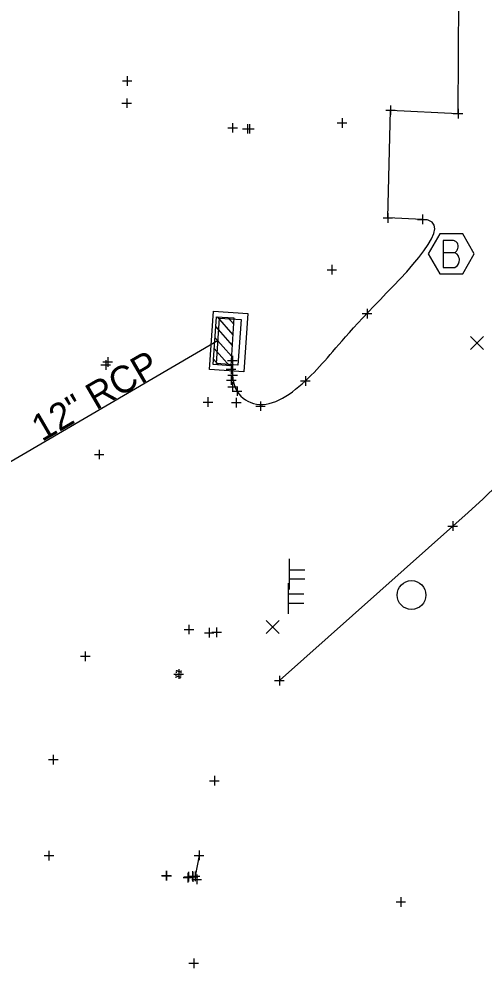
# Model space of a CAD drawing. Extents: x 2188719 to 2189819, y 654569 to 659504.
# Drawn here: x 2189350.5 to 2189399, y 655564.7 to 655663.5 of the extents above; entities that cross this region are included whole.
import ezdxf

# ---------------------------------------------------------------- set-up
doc = ezdxf.new("R2010")
doc.units = 0
for name, color, linetype in [('DR_X_Cells', 7, 'Continuous'), ('DR_X_Storm_Sewer', 7, 'Continuous'), ('DR_X_Text', 7, 'Continuous'), ('GK_Drainage_Nodes', 7, 'Continuous'), ('PM_X_Cells', 7, 'Continuous'), ('RD_X_Cells', 7, 'Continuous'), ('RD_X_Concrete_Pad', 7, 'Continuous'), ('RD_X_GR_Lt', 7, 'Continuous'), ('SN_X_Public', 7, 'Continuous'), ('SV_P_Mon_Cells_Set', 7, 'Continuous'), ('SV_X_Random_Point', 7, 'Continuous'), ('SV_X_Shot_Marker', 7, 'Continuous')]:
    doc.layers.add(name, color=color, linetype=linetype)

msp = doc.modelspace()

# ---------------------------------------------------------------- linework, layer by layer
at = {"layer": 'DR_X_Cells'}
for p, q in [((2189371.195, 655632.495), (2189372.833, 655630.627)), ((2189372.326, 655632.419), (2189372.909, 655631.755)), ((2189371.05, 655631.447), (2189372.757, 655629.5)), ((2189370.975, 655630.32), (2189372.682, 655628.373)), ((2189370.899, 655629.192), (2189372.472, 655627.398)), ((2189370.824, 655628.065), (2189371.342, 655627.474))]:
    msp.add_line(p, q, dxfattribs=at)
for points in [[(2189374.401, 655632.823), (2189373.994, 655626.753), (2189370.418, 655626.993), (2189370.825, 655633.063)], [(2189372.95, 655632.377), (2189372.616, 655627.389), (2189370.786, 655627.511), (2189371.121, 655632.5)], [(2189373.69, 655632.202), (2189373.372, 655627.463), (2189371.127, 655627.614), (2189371.445, 655632.353)]]:
    msp.add_lwpolyline(points, close=True, dxfattribs=at)
at = {"layer": 'DR_X_Storm_Sewer'}
msp.add_line((2189371.314, 655630.005), (2189348.002, 655616.423), dxfattribs=at)
at = {"layer": 'GK_Drainage_Nodes'}
for p, q in [((2189372.568, 655632.278), (2189372.568, 655632.278)), ((2189370.621, 655630.028), (2189370.621, 655630.028)), ((2189371.286, 655629.983), (2189371.286, 655629.983)), ((2189372.409, 655629.908), (2189372.409, 655629.908)), ((2189372.783, 655629.883), (2189372.783, 655629.883)), ((2189372.783, 655629.883), (2189372.783, 655629.883)), ((2189373.531, 655629.833), (2189373.531, 655629.833)), ((2189374.196, 655629.788), (2189374.196, 655629.788)), ((2189372.25, 655627.538), (2189372.25, 655627.538))]:
    msp.add_line(p, q, dxfattribs=at)
at = {"layer": 'PM_X_Cells'}
for p, q in [((2189366.905, 655594.935), (2189366.917, 655595.034)), ((2189366.924, 655595.102), (2189366.936, 655595.201)), ((2189366.944, 655595.268), (2189366.955, 655595.368)), ((2189366.963, 655595.435), (2189366.974, 655595.534)), ((2189366.982, 655595.601), (2189366.994, 655595.701)), ((2189367.192, 655595.29), (2189367.192, 655595.29)), ((2189367.41, 655595.046), (2189367.421, 655595.145)), ((2189367.429, 655595.212), (2189367.44, 655595.312)), ((2189367.448, 655595.379), (2189367.46, 655595.478)), ((2189367.467, 655595.545), (2189367.479, 655595.645)), ((2189367.39, 655594.879), (2189367.402, 655594.978))]:
    msp.add_line(p, q, dxfattribs=at)
for centre, start, end in [((2189367.254, 655595.824), 205.38356, 221.32603), ((2189367.13, 655594.756), 102.29753, 118.23046), ((2189367.254, 655595.824), 228.58791, 244.5195), ((2189367.13, 655594.756), 71.80011, 95.02993), ((2189367.254, 655595.824), 251.79129, 275.01886), ((2189367.254, 655595.824), 282.2969, 298.23046), ((2189367.254, 655595.824), 305.49145, 321.43588), ((2189367.13, 655594.756), 125.4944, 141.43588), ((2189367.13, 655594.756), 48.58791, 64.5208), ((2189367.13, 655594.756), 25.38356, 41.33027)]:
    msp.add_arc(centre, 0.288, start, end, dxfattribs=at)
at = {"layer": 'RD_X_Cells'}
for p, q in [((2189394.398, 655641.111), (2189393.198, 655639.032)), ((2189396.798, 655641.111), (2189394.398, 655641.111)), ((2189397.998, 655639.032), (2189396.798, 655641.111)), ((2189393.198, 655639.032), (2189394.398, 655636.954)), ((2189396.798, 655636.954), (2189397.998, 655639.032)), ((2189394.398, 655636.954), (2189396.798, 655636.954))]:
    msp.add_line(p, q, dxfattribs=at)
msp.add_lwpolyline([(2189395.962, 655639.153), (2189396.072, 655639.264), (2189396.138, 655639.33), (2189396.182, 655639.396), (2189396.204, 655639.44), (2189396.248, 655639.528), (2189396.27, 655639.594), (2189396.314, 655639.749), (2189396.314, 655639.815), (2189396.314, 655639.903), (2189396.293, 655640.035), (2189396.248, 655640.145), (2189396.182, 655640.234), (2189396.072, 655640.322), (2189395.984, 655640.366), (2189395.94, 655640.388), (2189395.829, 655640.432), (2189394.749, 655640.432), (2189394.749, 655637.632), (2189395.962, 655637.632), (2189396.116, 655637.72), (2189396.248, 655637.83), (2189396.358, 655638.007), (2189396.425, 655638.205), (2189396.447, 655638.404), (2189396.447, 655638.536), (2189396.403, 655638.668), (2189396.314, 655638.867), (2189396.204, 655638.999), (2189395.962, 655639.153), (2189394.749, 655639.153)], dxfattribs=at)
at = {"layer": 'RD_X_Concrete_Pad'}
for p, q in [((2189396.311, 655653.642), (2189396.425, 655669.553)), ((2189388.989, 655642.786), (2189389.271, 655654.003)), ((2189389.271, 655654.003), (2189396.311, 655653.642)), ((2189392.587, 655642.629), (2189388.989, 655642.786)), ((2189372.787, 655627.939), (2189372.818, 655626.395))]:
    msp.add_line(p, q, dxfattribs=at)
msp.add_open_spline([(2189372.818, 655626.395), (2189372.859, 655624.351), (2189376.129, 655621.909), (2189382.032, 655627.122), (2189385.284, 655631.64), (2189396.44, 655642.461), (2189392.587, 655642.629)], degree=3, dxfattribs=at)
at = {"layer": 'RD_X_GR_Lt'}
for p, q in [((2189395.751, 655610.7), (2189377.69, 655594.617)), ((2189369.32, 655576.413), (2189368.896, 655574.24))]:
    msp.add_line(p, q, dxfattribs=at)
msp.add_arc((2189352.785, 655661.984), 66.904, 309.95614, 7.43625, dxfattribs=at)
at = {"layer": 'SN_X_Public'}
for p, q in [((2189378.726, 655604.08), (2189378.726, 655607.28)), ((2189378.726, 655606.16), (2189380.326, 655606.16)), ((2189378.726, 655605.68), (2189378.726, 655605.68)), ((2189378.726, 655605.2), (2189380.326, 655605.2)), ((2189378.626, 655601.55), (2189378.626, 655604.75)), ((2189378.626, 655603.63), (2189380.226, 655603.63)), ((2189378.626, 655603.15), (2189378.626, 655603.15)), ((2189378.626, 655602.67), (2189380.226, 655602.67))]:
    msp.add_line(p, q, dxfattribs=at)
at = {"layer": 'SV_P_Mon_Cells_Set'}
msp.add_circle((2189391.464, 655603.518), 1.5, dxfattribs=at)
at = {"layer": 'SV_X_Random_Point'}
for p, q in [((2189397.613, 655629.098), (2189398.947, 655630.433)), ((2189397.613, 655630.433), (2189398.947, 655629.098)), ((2189376.325, 655599.531), (2189377.659, 655600.867)), ((2189376.325, 655600.867), (2189377.659, 655599.531))]:
    msp.add_line(p, q, dxfattribs=at)
at = {"layer": 'SV_X_Shot_Marker'}
for p, q in [((2189361.822, 655657.547), (2189361.822, 655656.547)), ((2189361.322, 655657.047), (2189362.322, 655657.047)), ((2189361.822, 655657.047), (2189361.822, 655657.047)), ((2189361.276, 655654.728), (2189362.276, 655654.728)), ((2189361.776, 655655.228), (2189361.776, 655654.228)), ((2189361.776, 655654.728), (2189361.776, 655654.728)), ((2189389.271, 655654.503), (2189389.271, 655653.503)), ((2189388.771, 655654.003), (2189389.771, 655654.003)), ((2189389.271, 655654.003), (2189389.271, 655654.003)), ((2189395.811, 655653.642), (2189396.811, 655653.642)), ((2189396.311, 655654.142), (2189396.311, 655653.142)), ((2189396.311, 655653.642), (2189396.311, 655653.642)), ((2189372.812, 655652.663), (2189372.812, 655651.663)), ((2189374.36, 655652.557), (2189374.36, 655651.557)), ((2189374.567, 655652.555), (2189374.567, 655651.555)), ((2189383.721, 655652.672), (2189384.721, 655652.672)), ((2189384.221, 655653.172), (2189384.221, 655652.172)), ((2189384.221, 655652.672), (2189384.221, 655652.672)), ((2189372.312, 655652.163), (2189373.312, 655652.163)), ((2189372.812, 655652.163), (2189372.812, 655652.163)), ((2189373.86, 655652.057), (2189374.86, 655652.057)), ((2189374.067, 655652.055), (2189375.067, 655652.055)), ((2189374.36, 655652.057), (2189374.36, 655652.057)), ((2189374.567, 655652.055), (2189374.567, 655652.055)), ((2189388.489, 655642.786), (2189389.489, 655642.786)), ((2189388.989, 655643.286), (2189388.989, 655642.286)), ((2189388.989, 655642.786), (2189388.989, 655642.786)), ((2189392.087, 655642.629), (2189393.087, 655642.629)), ((2189392.587, 655643.129), (2189392.587, 655642.129)), ((2189392.587, 655642.629), (2189392.587, 655642.629)), ((2189383.153, 655637.886), (2189383.153, 655636.886)), ((2189382.653, 655637.386), (2189383.653, 655637.386)), ((2189383.153, 655637.386), (2189383.153, 655637.386)), ((2189386.327, 655632.815), (2189387.327, 655632.815)), ((2189386.827, 655633.315), (2189386.827, 655632.315)), ((2189386.827, 655632.815), (2189386.827, 655632.815)), ((2189359.294, 655627.783), (2189360.294, 655627.783)), ((2189359.583, 655627.97), (2189359.583, 655626.97)), ((2189359.794, 655628.283), (2189359.794, 655627.283)), ((2189359.794, 655627.783), (2189359.794, 655627.783)), ((2189372.287, 655627.939), (2189373.287, 655627.939)), ((2189372.287, 655627.939), (2189373.287, 655627.939)), ((2189372.787, 655628.439), (2189372.787, 655627.439)), ((2189372.787, 655628.439), (2189372.787, 655627.439)), ((2189372.787, 655627.939), (2189372.787, 655627.939)), ((2189372.787, 655627.939), (2189372.787, 655627.939)), ((2189359.083, 655627.47), (2189360.083, 655627.47)), ((2189359.583, 655627.47), (2189359.583, 655627.47)), ((2189372.15, 655627.019), (2189373.15, 655627.019)), ((2189372.65, 655627.519), (2189372.65, 655626.519)), ((2189372.65, 655627.019), (2189372.65, 655627.019)), ((2189372.818, 655626.895), (2189372.818, 655625.895)), ((2189372.167, 655625.903), (2189373.167, 655625.903)), ((2189372.318, 655626.395), (2189373.318, 655626.395)), ((2189372.667, 655626.403), (2189372.667, 655625.403)), ((2189372.667, 655625.903), (2189372.667, 655625.903)), ((2189372.804, 655625.71), (2189372.804, 655624.71)), ((2189372.818, 655626.395), (2189372.818, 655626.395)), ((2189379.905, 655625.807), (2189380.905, 655625.807)), ((2189380.405, 655626.307), (2189380.405, 655625.307)), ((2189380.405, 655625.807), (2189380.405, 655625.807)), ((2189372.304, 655625.21), (2189373.304, 655625.21)), ((2189372.784, 655624.746), (2189373.784, 655624.746)), ((2189372.804, 655625.21), (2189372.804, 655625.21)), ((2189373.284, 655625.246), (2189373.284, 655624.246)), ((2189373.284, 655624.746), (2189373.284, 655624.746)), ((2189370.24, 655624.114), (2189370.24, 655623.114)), ((2189373.188, 655624.059), (2189373.188, 655623.059)), ((2189369.74, 655623.614), (2189370.74, 655623.614)), ((2189370.24, 655623.614), (2189370.24, 655623.614)), ((2189372.688, 655623.559), (2189373.688, 655623.559)), ((2189373.188, 655623.559), (2189373.188, 655623.559)), ((2189375.222, 655623.182), (2189376.222, 655623.182)), ((2189375.722, 655623.682), (2189375.722, 655622.682)), ((2189375.722, 655623.182), (2189375.722, 655623.182)), ((2189358.408, 655618.152), (2189359.408, 655618.152)), ((2189358.908, 655618.652), (2189358.908, 655617.652)), ((2189358.908, 655618.152), (2189358.908, 655618.152)), ((2189395.751, 655611.2), (2189395.751, 655610.2)), ((2189395.251, 655610.7), (2189396.251, 655610.7)), ((2189395.751, 655610.7), (2189395.751, 655610.7)), ((2189368.261, 655600.43), (2189368.261, 655599.43)), ((2189370.372, 655600.096), (2189370.372, 655599.096)), ((2189371.141, 655600.145), (2189371.141, 655599.145)), ((2189367.761, 655599.93), (2189368.761, 655599.93)), ((2189368.261, 655599.93), (2189368.261, 655599.93)), ((2189369.872, 655599.596), (2189370.872, 655599.596)), ((2189370.372, 655599.596), (2189370.372, 655599.596)), ((2189370.641, 655599.645), (2189371.641, 655599.645)), ((2189371.141, 655599.645), (2189371.141, 655599.645)), ((2189356.954, 655597.149), (2189357.954, 655597.149)), ((2189357.454, 655597.649), (2189357.454, 655596.649)), ((2189357.454, 655597.149), (2189357.454, 655597.149)), ((2189366.692, 655595.29), (2189367.692, 655595.29)), ((2189367.192, 655595.79), (2189367.192, 655594.79)), ((2189367.192, 655595.29), (2189367.192, 655595.29)), ((2189377.69, 655595.117), (2189377.69, 655594.117)), ((2189377.19, 655594.617), (2189378.19, 655594.617)), ((2189377.69, 655594.617), (2189377.69, 655594.617)), ((2189353.622, 655586.391), (2189354.622, 655586.391)), ((2189354.122, 655586.891), (2189354.122, 655585.891)), ((2189354.122, 655586.391), (2189354.122, 655586.391)), ((2189370.413, 655584.182), (2189371.413, 655584.182)), ((2189370.913, 655584.682), (2189370.913, 655583.682)), ((2189370.913, 655584.182), (2189370.913, 655584.182)), ((2189353.171, 655576.389), (2189354.171, 655576.389)), ((2189353.671, 655576.889), (2189353.671, 655575.889)), ((2189353.671, 655576.389), (2189353.671, 655576.389)), ((2189368.82, 655576.413), (2189369.82, 655576.413)), ((2189369.32, 655576.913), (2189369.32, 655575.913)), ((2189369.32, 655576.413), (2189369.32, 655576.413)), ((2189365.394, 655574.312), (2189366.394, 655574.312)), ((2189365.43, 655574.301), (2189366.43, 655574.301)), ((2189365.894, 655574.812), (2189365.894, 655573.812)), ((2189365.894, 655574.312), (2189365.894, 655574.312)), ((2189365.93, 655574.801), (2189365.93, 655573.801)), ((2189365.93, 655574.301), (2189365.93, 655574.301)), ((2189368.151, 655574.608), (2189368.151, 655573.608)), ((2189368.227, 655574.691), (2189368.227, 655573.691)), ((2189368.644, 655574.766), (2189368.644, 655573.766)), ((2189368.683, 655574.665), (2189368.683, 655573.665)), ((2189368.896, 655574.74), (2189368.896, 655573.74)), ((2189369.08, 655574.413), (2189369.08, 655573.413)), ((2189367.651, 655574.108), (2189368.651, 655574.108)), ((2189367.727, 655574.191), (2189368.727, 655574.191)), ((2189368.144, 655574.266), (2189369.144, 655574.266)), ((2189368.151, 655574.108), (2189368.151, 655574.108)), ((2189368.183, 655574.165), (2189369.183, 655574.165)), ((2189368.227, 655574.191), (2189368.227, 655574.191)), ((2189368.396, 655574.24), (2189369.396, 655574.24)), ((2189368.58, 655573.913), (2189369.58, 655573.913)), ((2189368.644, 655574.266), (2189368.644, 655574.266)), ((2189368.683, 655574.165), (2189368.683, 655574.165)), ((2189368.896, 655574.24), (2189368.896, 655574.24)), ((2189369.08, 655573.913), (2189369.08, 655573.913)), ((2189389.844, 655571.571), (2189390.844, 655571.571)), ((2189390.344, 655572.071), (2189390.344, 655571.071)), ((2189390.344, 655571.571), (2189390.344, 655571.571)), ((2189368.758, 655565.688), (2189368.758, 655564.688)), ((2189368.258, 655565.188), (2189369.258, 655565.188)), ((2189368.758, 655565.188), (2189368.758, 655565.188))]:
    msp.add_line(p, q, dxfattribs=at)

# ---------------------------------------------------------------- texts
at = {"layer": 'DR_X_Text'}
msp.add_text('12" RCP', height=2.8, rotation=30.22588, dxfattribs=at).set_placement((2189352.937, 655619.426))

doc.saveas('drawing.dxf')
